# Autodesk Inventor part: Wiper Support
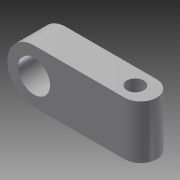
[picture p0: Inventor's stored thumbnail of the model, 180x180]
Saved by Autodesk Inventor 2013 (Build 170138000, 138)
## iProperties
Created: 2006-03
Part Number: Wiper Support
Document SubType Name: Modeling
Designer: debonom
Material: Stainless Steel, 440C
Mass: 138.885 g
Surface Area: 61.269 cm^2
Volume: 17.9206 cm^3
Density: 7.75 g/cm^3
Author: debonom
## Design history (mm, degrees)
sketch "Sketch1"
  geometry: L1 (-37.5, 0)-(50, 0) reference; L2 (25, 12.5)-(-25, 12.5); L3 (-25, 12.5)-(-25, -12.5); L4 (-25, -12.5)-(25, -12.5); L5 (25, -12.5)-(25, 12.5); L6 (25, 12.5)-(-25, -12.5); A1 r 12.5 centre (25, 0) between (25, -12.5) and (25, 12.5); 1 further point
  constraints: 10 end point, 2 midpoint, 2 parallel, 2 point on circle, 1 centre point, 1 horizontal, 1 perpendicular, 1 point on line
  dimensions: "d11" = 25 distance of L4.end L2.start; "d12" = 50 distance of L2.start L2.end
extrude "Extrusion1" new body sketch "Sketch1" stored distance "d3" = 15; taper "d4" = 0 deg
sketch "Sketch4"
  geometry: C1 r 7.5 at (25, 0); A1 r 12.5 centre (25, 0) between (25, -12.5) and (25, 12.5) reference; 1 further point
  constraints: 1 centre point, 1 coincident
  dimensions: "d13" = 15 diameter of C1
extrude "Extrusion3" cut sketch "Sketch4" stored distance "d14" = 15; taper "d15" = 0 deg
sketch "Sketch3"
  geometry: L1 (-5, 0)-(30, 0) reference; L2 (25, -7.5)-(25, 7.5) reference; C1 r 4 at (15, 0); 1 further point
  constraints: 1 centre point, 1 point on line
  dimensions: "d8" = 8 diameter of C1; "d16" = 10 distance from line of L2 C1.centre
extrude "Extrusion2" cut sketch "Sketch3" stored distance "d9" = 15; taper "d10" = 0 deg
fillet "Fillet2"
body "Solid1"
